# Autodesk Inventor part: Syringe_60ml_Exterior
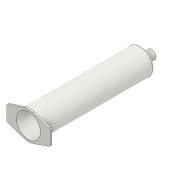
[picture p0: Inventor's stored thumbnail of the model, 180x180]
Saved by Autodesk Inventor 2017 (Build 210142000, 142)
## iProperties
Created: 2018-03
Part Number: Syringe_60ml_Exterior
Material: Glass
Document SubType Name: Modeling
Designer: JK
Density: 2.18 g/cm^3
Appearance: Clear
Sending System: Autodesk Translation Framework v6.5.0.72
Preprocessor: ST-DEVELOPER v16.13
Title: C:/Users/Marco/Documents/Marco/3D printing/Syringe_60ml_Exterior.step
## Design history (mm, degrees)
feature "Body1"
sketch "Sketch1"
  geometry: C1 r 15.771 at (0, 0); 1 further point
  constraints: 1 centre point, 1 coincident
extrude "Extrusion1" cut sketch "Sketch1" distance "d0" = 29.25; taper "d1" = 0 deg
body "Solid1"
